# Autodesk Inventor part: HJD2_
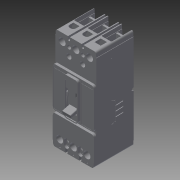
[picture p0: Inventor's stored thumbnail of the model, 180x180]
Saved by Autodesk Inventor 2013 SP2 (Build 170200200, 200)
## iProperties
Created: 2014-08
Part Number: HJD2_
Material: Generic
Document SubType Name: Modeling
Designer: EM/EM
Density: 1 g/cm^3
Description: TYPE HJD THERMAL MAGNETIC CIRCUIT BREAKERS TWO POLE, SERIES C
MXEDIT: false
MXINVTNRV: INV Versioned Component|HJD2_|004.0
Author: EM/EM
Revision Number: 004
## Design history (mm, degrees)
derived "JD2_.iam"
node "L1"
node "L2"
node "T1"
node "T2"
sketch "Sketch2"
  geometry: L1 (20.383, -4.338)-(23.012, -4.338) reference; L2 (23.012, -4.338)-(23.012, -1.981) reference; L3 (23.012, -1.981)-(20.879, -1.981) reference; L4 (20.879, -1.981)-(20.879, 0) reference; L5 (20.879, 0)-(23.012, 0) reference; L6 (23.012, 0)-(23.012, 7.584) reference; L7 (23.012, 16.242)-(23.012, 26.975) reference; L8 (23.012, 26.975)-(19.456, 26.975) reference; L9 (19.456, 26.975)-(19.456, 31.75) reference; L10 (3.581, 31.75)-(19.456, 31.75) reference; L11 (3.581, 31.75)-(3.581, 26.975) reference; L12 (3.581, 26.975)-(0, 26.975) reference; L13 (0, 26.975)-(0, 16.242) reference; L14 (0, 7.584)-(0, 0) reference; L15 (0, 0)-(20.383, 0) reference; L16 (20.383, 0)-(20.383, -2.388) reference; L17 (20.383, -2.388)-(22.365, -2.388) reference; L18 (22.365, -2.388)-(22.365, -3.962) reference; L19 (22.365, -3.962)-(20.383, -3.962) reference; L20 (20.383, -3.962)-(20.383, -4.338) reference; C1 r 10.795 at (11.493, 11.913) reference; C2 r 10.795 at (11.493, 11.913); A1 r 12.294 centre (11.506, 11.913) between (23.012, 7.584) and (23.012, 16.242) reference; A2 r 12.294 centre (11.506, 11.913) between (0, 16.242) and (0, 7.584) reference; 1 further point
  constraints: 1 centre point, 1 coincident, 1 concentric
extrude "Extrusion2" cut sketch "Sketch2" distance "d3" = 15.875; taper "d4" = 0 deg
sketch "Sketch3"
  geometry: C1 r 6.35 at (0, 0) reference; C2 r 6.35 at (0, 0); 1 further point
  constraints: 1 centre point, 1 coincident, 1 concentric
extrude "Extrusion3" cut sketch "Sketch3" distance "d5" = 9.525; taper "d6" = 0 deg
sketch "Sketch4"
  geometry: C1 r 10.795 at (8.89, 11.913) reference; C2 r 10.795 at (8.89, 11.913); 1 further point
  constraints: 1 centre point, 1 coincident, 1 concentric
extrude "Extrusion4" cut sketch "Sketch4" distance "d7" = 9.525; taper "d8" = 0 deg
sketch "Sketch5"
  geometry: C1 r 6.35 at (0, 0) reference; C2 r 6.35 at (0, 0); 1 further point
  constraints: 1 centre point, 1 coincident, 1 concentric
extrude "Extrusion5" cut sketch "Sketch5" distance "d9" = 9.525; taper "d11" = 0 deg; dims "d10" = 4.7752, "d12" = 0
sketch "Sketch6"
  geometry: C1 r 8.738 at (-34.938, 0) reference; 1 further point
extrude "Extrusion6" cut sketch "Sketch6" distance "d15" = 9.525; taper "d16" = 0 deg
sketch "Sketch8"
  geometry: C1 r 6.35 at (0, 0) reference; C2 r 6.35 at (0, 0); 1 further point
  constraints: 1 centre point, 1 coincident, 1 concentric
extrude "Extrusion7" cut sketch "Sketch8" distance "d17" = 7.9375; taper "d19" = 0 deg; dims "d18" = 3.9624, "d20" = 0
sketch "Sketch9"
  geometry: C1 r 8.738 at (34.912, 0) reference; C2 r 10.795 at (34.912, 0); 1 further point
  constraints: 1 centre point, 1 coincident
  dimensions: "d21" = 21.59 diameter of C2
extrude "Extrusion8" cut sketch "Sketch9" distance "d22" = 10.4775; taper "d23" = 0 deg
sketch "Sketch10"
  geometry: C1 r 6.35 at (0, 0) reference; C2 r 6.35 at (0, 0); 1 further point
  constraints: 1 centre point, 1 coincident, 1 concentric
extrude "Extrusion9" cut sketch "Sketch10" distance "d24" = 10.4775; taper "d26" = 0 deg; dims "d25" = 5.2324, "d27" = 0
body "Solid1"
node "JD2_.ipt:1"
